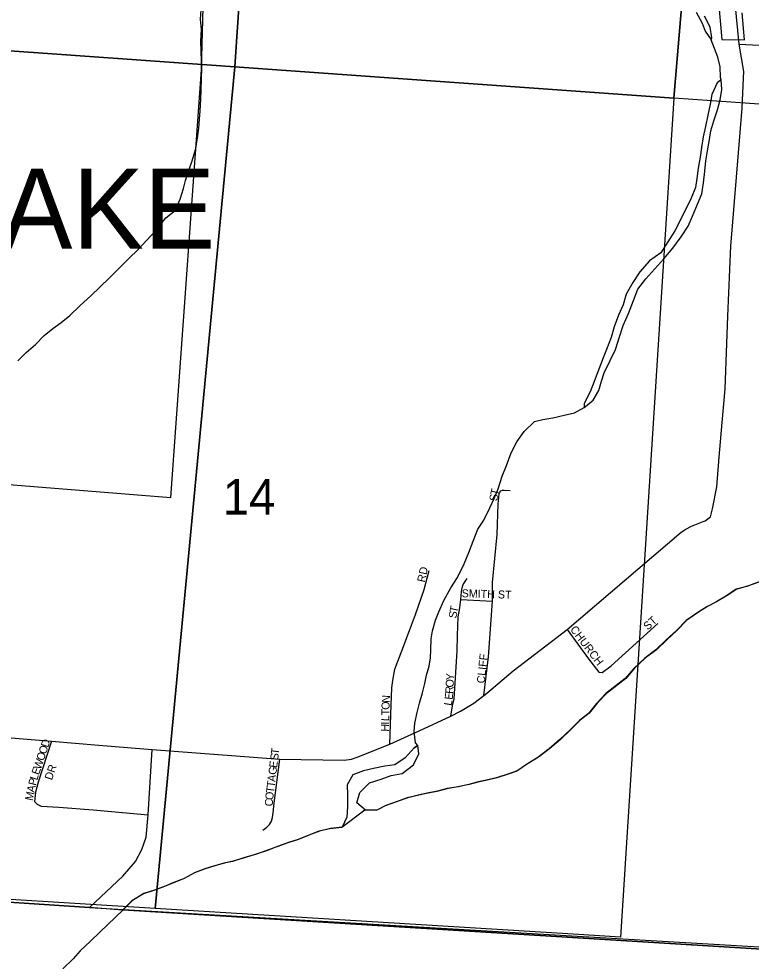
# Model space of a CAD drawing. Extents: x 0 to 40.4, y 0 to 22.
# Drawn here: x 6.339 to 7.206, y 14.615 to 15.73 of the extents above; entities that cross this region are included whole.
import ezdxf

# ---------------------------------------------------------------- set-up
doc = ezdxf.new("R2010")
doc.units = 0
for name, color, linetype in [('GM_X_City_Street', 7, 'Continuous'), ('GM_X_City_Street_Text', 7, 'Continuous'), ('GM_X_Corporation', 7, 'Continuous'), ('GM_X_Corporation_Text', 7, 'Continuous'), ('GM_X_County', 7, 'Continuous'), ('GM_X_Major_Lake', 7, 'Continuous'), ('GM_X_Major_River', 7, 'Continuous'), ('GM_X_Section', 7, 'Continuous'), ('GM_X_Section_Text', 7, 'Continuous'), ('GM_X_State_Route', 7, 'Continuous')]:
    doc.layers.add(name, color=color, linetype=linetype)

msp = doc.modelspace()

# ---------------------------------------------------------------- linework, layer by layer
at = {"layer": 'GM_X_City_Street'}
for points in [[(7.1916, 15.6998), (7.3976, 15.6894), (7.6176, 15.6748), (7.6181, 15.6909), (7.6244, 15.8052), (7.6307, 15.9128), (7.636, 16.0217)], [(6.8892, 14.9291), (6.8949, 14.9751), (6.8996, 15.0409), (6.8997, 15.0627), (6.9051, 15.1195), (6.9064, 15.1559), (6.9066, 15.1597), (6.9076, 15.1676), (6.9082, 15.1697), (6.9095, 15.1712), (6.9114, 15.1721), (6.9133, 15.1723), (6.9206, 15.1719)], [(6.7779, 14.8717), (6.7794, 14.9183), (6.7804, 14.9378), (6.7811, 14.9444), (6.7826, 14.9536), (6.784, 14.9602), (6.7921, 14.9822), (6.8023, 15.0093), (6.8082, 15.0251), (6.8185, 15.0545), (6.8247, 15.0769)], [(6.8504, 14.9048), (6.8527, 14.9193), (6.8543, 14.9251), (6.8576, 14.9818), (6.8582, 15.0002), (6.8589, 15.0221), (6.8609, 15.0328), (6.862, 15.0428), (6.863, 15.0522), (6.8635, 15.0565), (6.8649, 15.0604), (6.8695, 15.0675)], [(6.862, 15.0428), (6.8996, 15.0409)], [(6.9878, 15.0072), (7.0133, 14.9727), (7.0255, 14.9568), (7.0294, 14.9563), (7.04, 14.9641), (7.0951, 15.0145)], [(6.3777, 14.875), (6.362, 14.8267), (6.3587, 14.8149), (6.3577, 14.8073), (6.3573, 14.8039), (6.3607, 14.8008), (6.3653, 14.7981), (6.3863, 14.7972), (6.4269, 14.7938), (6.4918, 14.7882)], [(6.6277, 14.77), (6.6326, 14.7735), (6.6356, 14.7765), (6.6378, 14.7807), (6.6393, 14.7849), (6.64, 14.7902), (6.6411, 14.802), (6.648, 14.8537)]]:
    msp.add_lwpolyline(points, dxfattribs=at)
at = {"layer": 'GM_X_Corporation'}
for points in [[(6.1961, 14.5886), (6.2034, 14.693), (5.9456, 14.7103), (5.8513, 14.7168), (5.8591, 14.9075), (5.9465, 14.9054), (5.9681, 15.2076), (6.5188, 15.1635), (6.5553, 15.6693), (6.5616, 15.9075)], [(7.1622, 15.803), (7.1709, 15.7051), (7.1978, 15.705), (7.1949, 15.7369)], [(7.2138, 15.0631), (7.2006, 15.0582), (7.1881, 15.0548), (7.1763, 15.0473), (7.1638, 15.0398), (7.1532, 15.0341), (7.1437, 15.0281), (7.1289, 15.0179), (7.1172, 15.0062), (7.105, 14.9949), (7.0929, 14.9832), (7.08, 14.9734), (7.0667, 14.9613), (7.0564, 14.9492), (7.0458, 14.9409), (7.0337, 14.9314), (7.0227, 14.9197), (7.0132, 14.908), (7.0025, 14.8997), (6.9919, 14.8891), (6.9794, 14.877), (6.9665, 14.8661), (6.9532, 14.8559), (6.9411, 14.8484), (6.9282, 14.8397), (6.918, 14.8363), (6.9047, 14.8318), (6.8918, 14.8288), (6.882, 14.8266), (6.8721, 14.824), (6.8585, 14.821), (6.8453, 14.8188), (6.8335, 14.8158), (6.8214, 14.8132), (6.8108, 14.811), (6.7987, 14.808), (6.7858, 14.8035), (6.7726, 14.7986), (6.7627, 14.7937), (6.7484, 14.7934), (6.7211, 14.773), (6.7071, 14.7715), (6.6938, 14.7686), (6.6813, 14.7637), (6.6688, 14.7584), (6.6586, 14.7554), (6.6442, 14.7502), (6.6313, 14.7453), (6.6203, 14.7415), (6.6052, 14.737), (6.5919, 14.7329), (6.5817, 14.7307), (6.5696, 14.7273), (6.5594, 14.7243), (6.5469, 14.7194), (6.534, 14.7123), (6.5211, 14.7074), (6.5113, 14.7033), (6.4988, 14.6984), (6.4863, 14.6947), (6.4726, 14.6864), (6.4618, 14.6752), (6.4224, 14.6785), (6.369, 14.682), (6.2494, 14.69)]]:
    msp.add_lwpolyline(points, dxfattribs=at)
at = {"layer": 'GM_X_County'}
msp.add_lwpolyline([(2.6, 14.9098), (3.7816, 14.849), (3.7947, 14.8444), (4.3781, 14.8049), (4.5187, 14.7962), (4.7718, 14.7855), (4.9113, 14.7777), (5.1259, 14.7632), (5.4221, 14.7453), (5.6303, 14.7317), (5.757, 14.7237), (5.765, 14.7235), (5.7951, 14.7228), (5.8513, 14.7168), (5.9456, 14.7103), (6.2034, 14.693), (6.2494, 14.69), (6.369, 14.682), (6.4224, 14.6785), (7.5441, 14.6124), (8.0846, 14.9692), (9.4, 14.8681)], dxfattribs=at)
at = {"layer": 'GM_X_Major_Lake'}
msp.add_line((6.4626, 14.6755), (7.4365, 14.6157), dxfattribs=at)
for points in [[(8.0483, 14.5781), (8.0892, 15.1222), (7.4365, 14.6157), (6.4626, 14.6755)], [(7.2146, 15.0634), (7.2013, 15.0585), (7.1888, 15.0551), (7.1771, 15.0476), (7.1646, 15.04), (7.154, 15.0344), (7.1445, 15.0284), (7.1297, 15.0182), (7.1179, 15.0065), (7.1058, 14.9951), (7.0936, 14.9834), (7.0807, 14.9736), (7.0674, 14.9615), (7.0572, 14.9494), (7.0466, 14.9411), (7.0344, 14.9317), (7.0234, 14.92), (7.0139, 14.9083), (7.0033, 14.9), (6.9927, 14.8894), (6.9801, 14.8773), (6.9672, 14.8664), (6.954, 14.8562), (6.9418, 14.8486), (6.9289, 14.84), (6.9187, 14.8366), (6.9054, 14.8321), (6.8926, 14.8291), (6.8827, 14.8269), (6.8729, 14.8243), (6.8593, 14.8213), (6.846, 14.8191), (6.8343, 14.8161), (6.8222, 14.8135), (6.8116, 14.8112), (6.7995, 14.8082), (6.7866, 14.8037), (6.7733, 14.7989), (6.7635, 14.794), (6.7491, 14.7936), (6.7389, 14.8024), (6.7424, 14.8145), (6.7538, 14.8259), (6.7678, 14.8303), (6.7795, 14.8345), (6.7928, 14.8371), (6.8061, 14.8473), (6.8125, 14.8601), (6.8111, 14.87)], [(6.8069, 14.8674), (6.7963, 14.8556), (6.7841, 14.8473), (6.772, 14.8455), (6.7588, 14.8429), (6.7467, 14.8399), (6.7342, 14.8354), (6.7277, 14.8237), (6.728, 14.8112), (6.728, 14.7975), (6.7272, 14.7854), (6.7218, 14.7733), (6.7078, 14.7718), (6.6946, 14.7688), (6.6821, 14.7639), (6.6696, 14.7587), (6.6593, 14.7557), (6.645, 14.7504), (6.6321, 14.7456), (6.6211, 14.7418), (6.6059, 14.7373), (6.5927, 14.7332), (6.5825, 14.731), (6.5704, 14.7276), (6.5601, 14.7246), (6.5476, 14.7197), (6.5348, 14.7126), (6.5219, 14.7077), (6.512, 14.7035), (6.4995, 14.6987), (6.487, 14.6949), (6.4734, 14.6866), (6.4626, 14.6755)], [(6.8111, 14.87), (6.8069, 14.8674)], [(6.4626, 14.6755), (6.4349, 14.6494), (6.4236, 14.6384), (6.4115, 14.627), (6.4032, 14.6175), (6.3911, 14.6057)]]:
    msp.add_lwpolyline(points, dxfattribs=at)
at = {"layer": 'GM_X_Major_River'}
for points in [[(6.3376, 15.325), (6.3475, 15.3348), (6.3585, 15.3446), (6.3691, 15.3552), (6.3793, 15.3635), (6.3892, 15.3703), (6.3991, 15.3786), (6.4112, 15.3903), (6.4245, 15.4024), (6.4348, 15.4122), (6.4465, 15.4236), (6.4689, 15.4459), (6.4807, 15.4572), (6.4898, 15.467), (6.502, 15.4802), (6.513, 15.4942), (6.524, 15.5029), (6.5297, 15.5165), (6.5339, 15.529), (6.5362, 15.5385), (6.5393, 15.5484), (6.5439, 15.5616), (6.5485, 15.5764), (6.5504, 15.5889), (6.552, 15.6003), (6.5528, 15.6109), (6.5536, 15.6207), (6.5544, 15.6348), (6.5548, 15.6454), (6.5552, 15.6587), (6.5557, 15.6704), (6.555, 15.6799), (6.5543, 15.7034), (6.5551, 15.7171), (6.554, 15.7292), (6.5548, 15.7402)], [(7.1406, 15.7375), (7.1477, 15.7246), (7.1511, 15.7151), (7.1582, 15.7049)], [(7.1582, 15.7049), (7.159, 15.7071), (7.1571, 15.7197), (7.1504, 15.733)], [(7.1701, 15.6574), (7.1694, 15.6605), (7.169, 15.673), (7.1664, 15.6844), (7.1582, 15.7049)], [(7.0082, 15.2701), (7.0095, 15.2711), (7.0188, 15.2784), (7.0253, 15.2901), (7.0287, 15.3011), (7.0318, 15.3109), (7.0387, 15.3257), (7.0452, 15.3386), (7.0498, 15.3537), (7.0543, 15.367), (7.0605, 15.381), (7.0666, 15.3965), (7.0715, 15.4098), (7.081, 15.4223), (7.0917, 15.434), (7.1023, 15.4457), (7.113, 15.4585), (7.1228, 15.4718), (7.1312, 15.4843), (7.1362, 15.4964), (7.1423, 15.5104), (7.1472, 15.5225), (7.1492, 15.5358), (7.1508, 15.5494), (7.1519, 15.5619), (7.1539, 15.5737), (7.1562, 15.5869), (7.1581, 15.5972), (7.1616, 15.6089), (7.1658, 15.6222), (7.1689, 15.6339), (7.1708, 15.646), (7.1701, 15.6574)], [(7.1656, 15.654), (7.1591, 15.6404), (7.1571, 15.6286), (7.1544, 15.6158), (7.1517, 15.6025), (7.1487, 15.59), (7.1467, 15.5775), (7.1455, 15.5661), (7.1428, 15.5532), (7.1413, 15.5407), (7.1397, 15.5301), (7.1347, 15.5176), (7.1225, 15.4926), (7.1153, 15.479), (7.1069, 15.4658), (7.0986, 15.4529), (7.0853, 15.4435), (7.0739, 15.4306), (7.0655, 15.4178), (7.0579, 15.4038), (7.0541, 15.3913), (7.0487, 15.3791), (7.0434, 15.3655), (7.0399, 15.3526), (7.0346, 15.3386), (7.0307, 15.3288), (7.02, 15.3008), (7.0151, 15.2883), (7.0082, 15.2746), (7.0082, 15.2701)], [(7.1701, 15.6574), (7.1656, 15.654)], [(6.8111, 14.87), (6.8084, 14.873), (6.807, 14.8867), (6.8078, 14.8966), (6.8105, 14.9091), (6.8132, 14.92), (6.8166, 14.9325), (6.8193, 14.9435), (6.8216, 14.9534), (6.8247, 14.964), (6.8262, 14.9738), (6.8267, 14.9833), (6.8271, 14.9962), (6.8286, 15.0057), (6.8321, 15.0182), (6.8359, 15.028), (6.842, 15.0417), (6.8504, 15.0564), (6.858, 15.0689), (6.866, 15.0848), (6.8717, 15.0984), (6.8767, 15.1117), (6.8821, 15.1261), (6.8893, 15.1367), (6.8965, 15.1514), (6.9015, 15.1624), (6.9061, 15.1738), (6.9111, 15.1885), (6.916, 15.2014), (6.9218, 15.2162), (6.9282, 15.2294), (6.937, 15.2415), (6.9491, 15.2532), (6.959, 15.2559), (6.9711, 15.2577), (6.9843, 15.2607), (6.9965, 15.2637), (7.0082, 15.2701)], [(6.8069, 14.8674), (6.8111, 14.87)]]:
    msp.add_lwpolyline(points, dxfattribs=at)
at = {"layer": 'GM_X_Section'}
for points in [[(6.0805, 16.728), (6.3929, 16.7053), (6.6625, 16.6858), (6.5945, 15.6728), (6.012, 15.7142)], [(6.6625, 16.6858), (7.1996, 16.6471), (7.1143, 15.6359), (6.5945, 15.6728)], [(7.1996, 16.6471), (7.2909, 16.6427), (7.7054, 16.6198), (7.6314, 15.5996), (7.1143, 15.6359)], [(6.012, 15.7142), (6.5945, 15.6728), (6.5001, 14.6771), (5.9421, 14.7119)], [(6.5945, 15.6728), (7.1143, 15.6359), (7.051, 14.6433), (6.995, 14.6467), (6.5001, 14.6771)]]:
    msp.add_lwpolyline(points, close=True, dxfattribs=at)
at = {"layer": 'GM_X_State_Route'}
for points in [[(7.1916, 15.6998), (7.1833, 15.7851), (7.1797, 15.8149)], [(7.1966, 15.6601), (7.1969, 15.6673), (7.1916, 15.6998)], [(7.1487, 15.1349), (7.1511, 15.1359), (7.1574, 15.1405), (7.1601, 15.1502), (7.1652, 15.1759), (7.1677, 15.2111), (7.1714, 15.2521), (7.1749, 15.2921), (7.178, 15.3781), (7.1815, 15.4606), (7.1951, 15.6242), (7.1966, 15.6601)], [(6.4868, 14.8662), (6.4967, 14.8654), (6.648, 14.8537), (6.7238, 14.8527), (6.7326, 14.8539), (6.7392, 14.8564), (6.7779, 14.8717), (6.8127, 14.8872), (6.8504, 14.9048), (6.8615, 14.9105), (6.8775, 14.9203), (6.8892, 14.9291), (6.8928, 14.9318), (6.9238, 14.9582), (6.9878, 15.0072), (7.1227, 15.1224), (7.1285, 15.1259), (7.135, 15.1294), (7.1487, 15.1349)], [(5.8173, 14.7248), (5.822, 14.7253), (5.8456, 14.7308), (5.8638, 14.7362), (5.895, 14.7527), (5.9526, 14.7852), (6.0047, 14.8184), (6.0416, 14.8418), (6.0806, 14.8632), (6.099, 14.8711), (6.1272, 14.8789), (6.1491, 14.8838), (6.1702, 14.8863), (6.1857, 14.8875), (6.2126, 14.8871), (6.2578, 14.8849), (6.3777, 14.875), (6.4338, 14.8704), (6.4868, 14.8662)], [(6.4224, 14.6785), (6.4622, 14.7154), (6.4771, 14.733), (6.4846, 14.7472), (6.4895, 14.7614), (6.4918, 14.7882), (6.4967, 14.8654)]]:
    msp.add_lwpolyline(points, dxfattribs=at)

# ---------------------------------------------------------------- texts
at = {"layer": 'GM_X_City_Street_Text'}
for s, rotation, p in [('T', 75.9836, (6.9059, 15.1651)), ('S', 83.4848, (6.9052, 15.1588)), ('RD', 77.4673, (6.8194, 15.0625)), ('SMITH ST', 358.1534, (6.8629, 15.0455)), ('S', 81.3868, (6.8568, 15.02)), ('T', 78.2506, (6.8578, 15.0265)), ('ST', 42.5212, (7.0833, 15.0059)), ('CHURCH', 307.2677, (6.9909, 15.0073)), ('CLIFF', 83.9883, (6.8902, 14.9431)), ('Y', 87.0481, (6.8538, 14.9468)), ('R', 86.9513, (6.853, 14.931)), ('O', 87.0766, (6.8534, 14.9385)), ('N', 86.1059, (6.7779, 14.9203)), ('E', 84.3499, (6.8523, 14.9239)), ('O', 87.6386, (6.7775, 14.9121)), ('L', 80.394, (6.8511, 14.9166)), ('L', 88.4696, (6.7772, 14.8988)), ('T', 88.4696, (6.7774, 14.9055)), ('H', 88.4701, (6.7769, 14.8863)), ('I', 88.4696, (6.7771, 14.8946)), ('D', 71.2723, (6.3736, 14.867)), ('O', 71.2939, (6.3683, 14.8512)), ('O', 71.2679, (6.3709, 14.8591)), ('S', 82.7838, (6.6457, 14.8522)), ('T', 82.8083, (6.6465, 14.8588)), ('W', 71.278, (6.3648, 14.8409)), ('E', 82.797, (6.6445, 14.8431)), ('E', 71.3145, (6.3626, 14.8346)), ('DR', 71.5614, (6.3781, 14.8284)), ('G', 82.8025, (6.6435, 14.8349)), ('P', 76.1228, (6.3591, 14.822)), ('L', 72.3428, (6.3606, 14.8283)), ('T', 82.7935, (6.6416, 14.82)), ('A', 82.7693, (6.6424, 14.8266)), ('A', 77.834, (6.3573, 14.8139)), ('T', 82.797, (6.6408, 14.8134)), ('M', 77.8149, (6.3552, 14.8041)), ('C', 86.5252, (6.6394, 14.7978)), ('O', 83.2301, (6.6398, 14.8051))]:
    msp.add_text(s, height=0.00947, rotation=rotation, dxfattribs=at).set_placement(p)
at = {"layer": 'GM_X_Corporation_Text'}
msp.add_text('BUCKEYE LAKE', height=0.094697, rotation=0, dxfattribs=at).set_placement((5.6071, 15.4578))
at = {"layer": 'GM_X_Section_Text'}
msp.add_text('14', height=0.04186, rotation=0, dxfattribs=at).set_placement((6.5803, 15.1433))

doc.saveas('drawing.dxf')
